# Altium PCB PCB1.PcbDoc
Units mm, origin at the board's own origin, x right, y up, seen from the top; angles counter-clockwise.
Board outline 64.06 x 116 mm, 2 copper layers (Top Layer, Bottom Layer); 43 components, 51 nets, 211 pads, 5 vias.
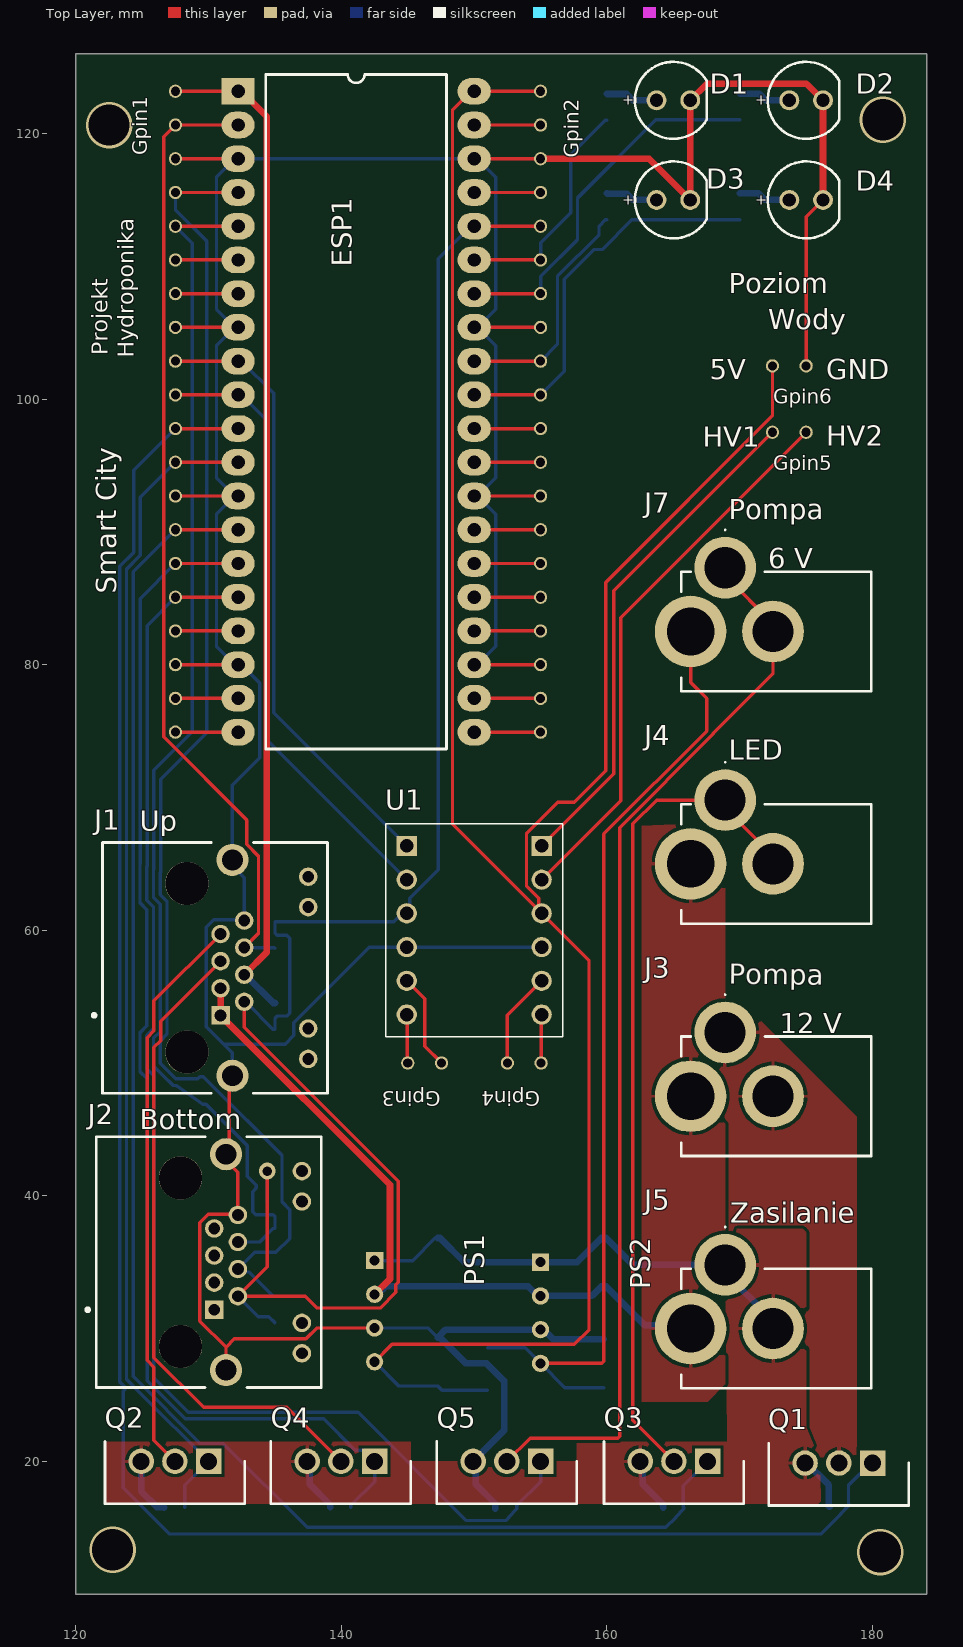
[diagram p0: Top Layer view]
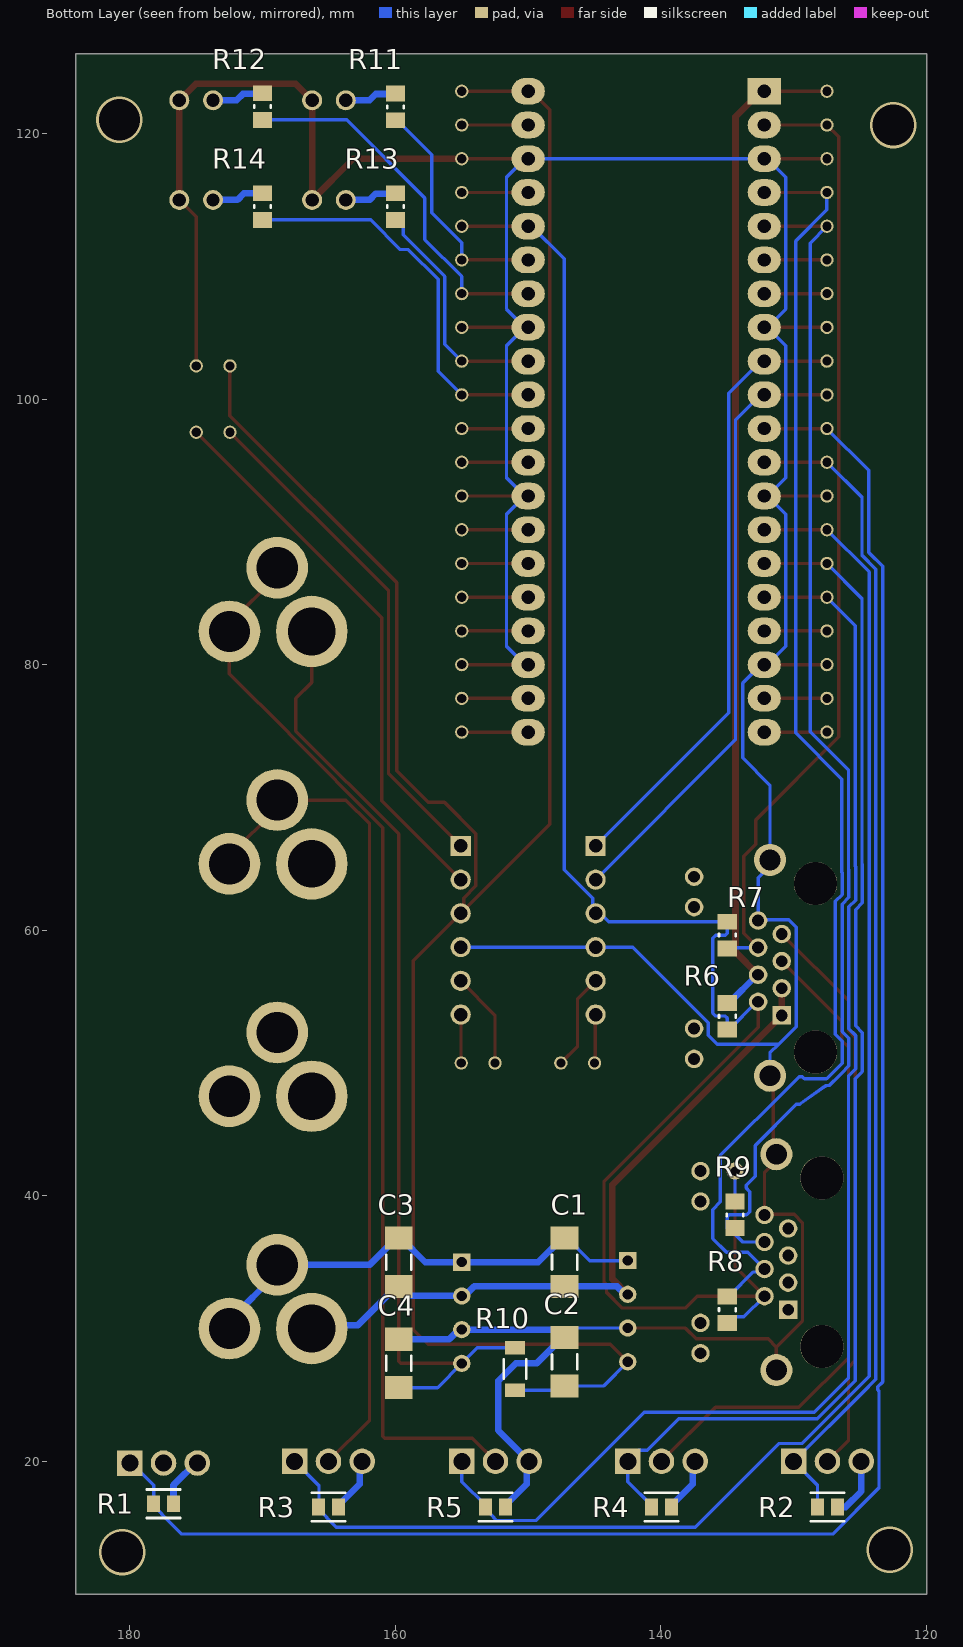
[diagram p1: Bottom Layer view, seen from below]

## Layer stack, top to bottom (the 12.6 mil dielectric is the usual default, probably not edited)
Top Solder: solder mask 0.0102, Solder Resist, Dk 3.5
Top Layer: signal copper 0.0356
Dielectric 1: dielectric 0.32, FR-4, Dk 4.8
Bottom Layer: signal copper 0.0356
Bottom Solder: solder mask 0.0102, Solder Resist, Dk 3.5

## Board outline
120,10 184.064,10 184.064,41.104 184.064,97.854 184.064,126 120,126

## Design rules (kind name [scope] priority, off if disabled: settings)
Clearance [All] p1: gap=0.254 ignorepadtopadclearanceinfootprint=FALSE
DiffPairsRouting [All] p1: maxlimit=0.254 minlimit=0.254 mostfreqgap=0.254 toplayer_minwidth=0.2 toplayer_maxwidth=0.381 toplayer_prefwidth=0.381 bottomlayer_minwidth=0.2 bottomlayer_maxwidth=0.381 bottomlayer_prefwidth=0.381 maxuncoupledlength=12.7
PolygonConnect [All] p1: connectstyle=Relief reliefconductorwidth=0.254 reliefentries=4 polygonreliefangle="90 Angle" airgapwidth=0.254
RoutingVias [All] p1: holewidth=0.711 width=1.27 viastyle="Through Hole" minholewidth=0.711 minwidth=1.27 maxholewidth=0.711 maxwidth=1.27
SolderMaskExpansion [All] p1: expansion=0.102 istentingtop=FALSE
SupplyNets "Schematic Supply Nets_3" [InNet('-vin_12')] p1: voltage=0.000
SupplyNets "Schematic Supply Nets_1" [InNet('- vout_5')] p2: voltage=0.000
SupplyNets "Schematic Supply Nets_8" [InNet('+vout_6')] p3: voltage=0.000
SupplyNets "Schematic Supply Nets_7" [InNet('+vin_12')] p4: voltage=0.000
SupplyNets "Schematic Supply Nets_6" [InNet('+vout_5')] p5: voltage=0.000
SupplyNets "Schematic Supply Nets" [InNet('3V3')] p6: voltage=0.000
Width [All] p1: maxlimit=6 minlimit=0.254 preferedwidth=0.254 minimp=50.000000 maximp=50.000000 favimp=50.000000 checkconnectedcopper=TRUE
29 further rules are at their usual default settings.

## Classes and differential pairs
component class "U_układ mocy": J3 J4 J7 Q1 Q2 Q3 Q4 Q5 R1 R2 R3 R4 R5
component class "U_12 na 5": C1 C2 C3 C4 J5 PS1 PS2 R10
component class Sheet1: D1 D2 D3 D4 ESP1 Gpin1 Gpin2 Gpin3 Gpin4 Gpin5 Gpin6 J1 J2 R6 R7 R8 R9 R11 R12 R13 R14 U1

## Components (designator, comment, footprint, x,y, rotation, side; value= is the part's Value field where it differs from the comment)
C1 "1000pF" CAPC4620X180X75LL50T35 147.25,35 r90 bottom
C2 "1000pF" CAPC4620X180X75LL50T35 147.25,27.5 r90 bottom
C3 "1000pF" CAPC4620X180X75LL50T35 159.75,35 r90 bottom
C4 "1000pF" CAPC4620X180X75LL50T35 159.75,27.38 r90 bottom
D1 "151053GS03000" WL-TMRW_D5.8H11.7 165,122.5 r0 top
D2 "151053GS03000" WL-TMRW_D5.8H11.7 175,122.5 r0 top
D3 "151053GS03000" WL-TMRW_D5.8H11.7 165,115 r0 top
D4 "151053GS03000" WL-TMRW_D5.8H11.7 175,115 r0 top
ESP1 "ESP32-S3-PICO" DIP40_ESP32 132.22,123.18 r0 top
Gpin1 "goldpin20" PCBComponent_1 127.5,100.32 r180 top
Gpin2 "goldpin20" PCBComponent_1 155,97.78 r0 top
Gpin3 "Goldpin 2" "Goldpin 2" 145,50 r270 top
Gpin4 "Goldpin 2" "Goldpin 2" 152.5,50 r270 top
Gpin5 "Goldpin 2" "Goldpin 2" 172.46,97.5 r270 top
Gpin6 "Goldpin 2" "Goldpin 2" 175,102.5 r90 top
J1 "2-406549-1" FP-2-406549-1-MFG 130.48,57.17 r270 top
J2 "2-406549-1" FP-2-406549-1-MFG 130,35 r270 top
J3 "PC-GK2.1" PCGK21 168.9,52.3 r180 top
J4 "PC-GK2.1" PCGK21 168.9,69.8 r180 top
J5 "PC-GK2.1" PCGK21 168.9,34.8 r180 top
J7 "PC-GK2.1" PCGK21 168.9,87.3 r180 top
PS1 "Isolated DC/DC Converters - Through Hole DC-DC CONVERTER, ISOLATED MODULE, SINGLE OUTPUT, 9.6V-14.4VDC INPUT, 5VDC OUTPUT, 1W   Source:  Datasheet" EC3T12S05P 142.5,35.12 r270 top
PS2 "Isolated DC/DC Converters - Through Hole DC-DC CONVERTER, ISOLATED MODULE, SINGLE OUTPUT, 9.6V-14.4VDC INPUT, 5VDC OUTPUT, 1W   Source:  Datasheet" EC3T12S05P 155,35 r270 top
Q1 "IRLZ44NPBF" TO254P469X1042X1967-3P 180,19.873 r180 top
Q2 "IRLZ44NPBF" TO254P469X1042X1967-3P 130,20 r180 top
Q3 "IRLZ44NPBF" TO254P469X1042X1967-3P 167.58,20 r180 top
Q4 "IRLZ44NPBF" TO254P469X1042X1967-3P 142.5,20 r180 top
Q5 "IRLZ44NPBF" TO254P469X1042X1967-3P 155,20 r180 top
R1 "ERA6AEB102V" FP-ERA6A-IPC_C 177.46,16.805 r180 bottom
R2 "ERA6AEB102V" FP-ERA6A-IPC_C 127.46,16.555 r180 bottom
R3 "ERA6AEB102V" FP-ERA6A-IPC_C 165.04,16.555 r180 bottom
R4 "ERA6AEB102V" FP-ERA6A-IPC_C 139.96,16.555 r180 bottom
R5 "ERA6AEB102V" FP-ERA6A-IPC_C 152.46,16.555 r180 bottom
R6 "RC0805FR-071KL" RESC2013X60X35ML10T20 135,53.52 r270 bottom
R7 "RC0805FR-071KL" RESC2013X60X35ML10T20 135,59.64 r90 bottom
R8 "RC0805FR-071KL" RESC2013X60X35ML10T20 135,31.42 r270 bottom
R9 "RC0805FR-071KL" RESC2013X60X35ML10T20 134.419,38.559 r90 bottom
R10 "AC1206JR-070RL" FP-AC1206-0_65-MFG 151,26.95 r90 bottom
R11 "RC0805FR-071KL" RESC2013X60X35ML10T20 160,122 r90 bottom
R12 "RC0805FR-071KL" RESC2013X60X35ML10T20 170,122.033 r90 bottom
R13 "RC0805FR-071KL" RESC2013X60X35ML10T20 160,114.5 r90 bottom
R14 "RC0805FR-071KL" RESC2013X60X35ML10T20 170,114.5 r90 bottom
U1 "BOB-12009" CONV_BOB-12009 150,60 r0 top

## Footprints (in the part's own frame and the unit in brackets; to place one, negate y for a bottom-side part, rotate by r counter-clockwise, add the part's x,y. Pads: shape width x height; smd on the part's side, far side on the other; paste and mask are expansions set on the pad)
CAPC4620X180X75LL50T35 [mm] "Chip Capacitor, 2-Leads, Body 5.1x2.2mm, IPC High Density"
  rect 1.75x2.1 smd: 1(-1.825,0) 2(1.825,0)
  silkscreen extent -0.55,-0.95 0.55,0.95, body extent -2.55,-1.1 2.55,1.1, height 1.8
CONV_BOB-12009 [mil]
  round 60 hole 40: GND_1(200,-50) GND_2(-200,-50) HV(200,50) HV2(200,150) HV3(200,-150) HV4(200,-250) LV(-200,50) LV2(-200,150) LV3(-200,-150) LV4(-200,-250)
  rect 60x60 / inner round 60 / far side rect 60x60 hole 40: HV1(200,250) LV1(-200,250)
  silkscreen extent -262,-316 262,316, body extent -262,-316 262,316, height 110
DIP40_ESP32 [mm]
  rect 2.5x2 hole 1: 1(0,0)
  oval 2.5x2 hole 1: 2(0,-2.54) 3(0,-5.08) 4(0,-7.62) 5(0,-10.16) 6(0,-12.7) 7(0,-15.24) 8(0,-17.78) 9(0,-20.32) 10(0,-22.86) 11(0,-25.4) 12(0,-27.94) 13(0,-30.48) 14(0,-33.02) 15(0,-35.56) 16(0,-38.1) 17(0,-40.64) 18(0,-43.18) 19(0,-45.72) 20(0,-48.26) 21(17.78,-48.26) 22(17.78,-45.72) 23(17.78,-43.18) 24(17.78,-40.64) 25(17.78,-38.1) 26(17.78,-35.56) 27(17.78,-33.02) 28(17.78,-30.48) 29(17.78,-27.94) 30(17.78,-25.4) 31(17.78,-22.86) 32(17.78,-20.32) 33(17.78,-17.78) 34(17.78,-15.24) 35(17.78,-12.7) 36(17.78,-10.16) 37(17.78,-7.62) 38(17.78,-5.08) 39(17.78,-2.54) 40(17.78,0)
  silkscreen extent 2.08,-49.53 15.7,1.27
EC3T12S05P [mm]
  rect 1.303x1.303 / inner round 1.204 / far side rect 1.303x1.303 hole 0.76: 1(0,0)
  round 1.303 hole 0.76: 2(2.54,0) 3(5.08,0) 4(7.62,0)
FP-2-406549-1-MFG [mm]
  rect 1.39x1.39 hole 0.89 paste-2539.97 mask+0: 1(3.58,0.42)
  round 1.39 hole 0.89 paste-2539.97 mask+0: 2(2.56,2.2) 3(1.54,0.42) 4(0.52,2.2) 5(-0.5,0.42) 6(-1.52,2.2) 7(-2.54,0.42) 8(-3.56,2.2) 9(-6.86,7.02) 10(-4.57,7.02) 11(4.57,7.02) 12(6.86,7.02)
  round 2.42 hole 1.57 paste-2539.97 mask+0: 13(-8.13,1.31) 14(8.13,1.31)
  round 3.25 hole 3.25 unplated paste-2539.97 mask+0: ""(-6.35,-2.12) ""(6.35,-2.12)
  silkscreen extent -9.44,-9.23 9.44,8.47, body extent -9.53,-8.57 9.53,8.57, height 0.25
FP-AC1206-0_65-MFG [mm]
  rect 1x1.5 smd paste+0 mask+0: 1(-1.6,0) 2(1.6,0)
  silkscreen extent -0.72,-0.85 0.72,0.85, body extent -1.55,-0.8 1.55,0.8, height 0.65
FP-ERA6A-IPC_C [mm]
  rect 1.005x1.262 smd paste+0 mask+0: 1(-0.751,0) 2(0.751,0)
  silkscreen extent -1.25,-1.07 1.25,1.07, body extent -1,-0.63 1,0.63, height 0.6
"Goldpin 2" [mm]
  round 1 / inner round 2.42 / far side round 1 hole 0.69 paste-2539.97 mask+0: 1(0,0) 2(0,2.54)
  body extent -1.27,-1.27 1.27,3.81, height 6.8
PCBComponent_1 [mm]
  round 1 / inner round 2.42 / far side round 1 hole 0.69 paste-2539.97 mask+0: 1(0,25.4) 2(0,22.86) 3(0,20.32) 4(0,17.78) 5(0,15.24) 6(0,12.7) 7(0,10.16) 8(0,7.62) 9(0,5.08) 10(0,2.54) 11(0,0) 12(0,-2.54) 13(0,-5.08) 14(0,-7.62) 15(0,-10.16) 16(0,-12.7) 17(0,-15.24) 18(0,-17.78) 19(0,-20.32) 20(0,-22.86)
  body extent -1.27,-24.13 1.27,26.67, height 6.8
PCGK21 [mm]
  round 4.65 hole 3.1: 2(0,0) 3(-3.6,4.8)
  round 5.385 hole 3.59: 4(2.6,4.8)
  silkscreen extent -11,-2.9 3.3,9.3, body extent -10.92,-0.09 3.38,9.33, height 12.54
RESC2013X60X35ML10T20 [mm] "Chip Resistor, 2-Leads, Body 2.1x1.35mm, IPC Low Density"
  rect 1.2x1.45 smd: 1(-1,0) 2(1,0)
  silkscreen extent -0.1,-0.63 0.1,0.63, body extent -1.05,-0.68 1.05,0.67, height 0.6
TO254P469X1042X1967-3P [mm]
  rect 1.92x1.92 hole 1.28: 1(0,0)
  round 1.92 hole 1.28: 2(2.54,0) 3(5.08,0)
  silkscreen extent -2.73,-1.5 7.81,3.19, body extent -2.67,-1.5 7.75,3.19, height 18.84
WL-TMRW_D5.8H11.7 [mm] "THT Mono-color Round LED, 2-leads"
  round 1.5 hole 1: 1(1.27,0) 2(-1.27,0)
  silkscreen extent -2.9,-2.9 2.5,2.9, body extent -2.9,-2.9 2.5,2.9, height 11.7

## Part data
C1 C2 C3 C4: library part CMP-2000-05503-1, "Chip Capacitor, 1000 pF, +/- 10%, 2000 V, -55 to 125 degC, 1808 (4520 Metric), RoHS, Tape and Reel", Capacitance=1nF, Case Size/Dimension=1808, Dielectric=X7R, Manufacturer=AVX, Package Description="2-Pin Surface Mount Device, Body 4.6 x 2 mm", Rated Voltage=2000V, Tolerance (%)=±10%
D1 D2 D3 D4: library part CMP-1489-00005-2, Case/Package=Radial, Color=Green, Forward Current=100mA, Forward Voltage=3.4V, Max Operating Temperature=85°C, Max Reverse Voltage (DC)=5V, Min Operating Temperature=-40°C, Test Current=20mA
J1 J2: library part CMP-2000-05541-2, "CONN MOD JACK 8P8C R/A SHIELDED", Color=Yellow, Current Rating=1.5A, Flammability Rating="UL94 V-0", Housing Color=Black, Max Operating Temperature=85°C, Max Voltage Rating (AC)=150V, Min Operating Temperature=-40°C, Package Quantity=63
J3 J4 J5 J7: "Connector", Manufacturer_Name=Ninigi
PS1 PS2: library part EC3T-12S05P, Manufacturer_Name="Adam Tech", Package=EC3T12S05P
Q1 Q2 Q3 Q4 Q5: "MOSFET (N-Channel)", Manufacturer_Name=Infineon, Mouser Part Number=942-IRLZ44NPBF
R1 R2 R3 R4 R5: library part CMP-2001-00581-2, "RES 1K OHM 0.1% 1/8W 0805", Case Code (Imperial)=0805, Case Code (Metric)=2012, Max Operating Temperature=155°C, Max Power Dissipation=125mW, Min Operating Temperature=-55°C, Package Quantity=5000, Resistance=1kR, Resistance Tolerance=0.1%, Resistor Type="Thin Film", Temperature Coefficient=25ppm/°C, Voltage Rating=100V
R6 R7 R8 R9 R11 R12 R13 R14: library part CMP-2100-03671-1, "Chip Resistor, 1 KOhm, +/- 1%, 125 mW, -55 to 155 degC, 0805 (2012 Metric), RoHS, Tape and Reel", Case Code (Imperial)=0805, Case Code (Metric)=2012, Manufacturer=Yageo, Max Operating Temperature=155degC, Max Power Dissipation=125mW, Min Operating Temperature=-55degC, Package Description="2-Pin Surface Mounted Device, Body 2 x 1.25 mm", Package Quantity=1, Resistance=1KOhm, Temperature Coefficient=100ppm/degreesC, Tolerance=1%, Voltage Rating=150V
R10: library part CMP-2003-04900-2, "RES SMD 0 OHM JUMPER 1/4W 1206", Case Code (Imperial)=1206, Case Code (Metric)=3216, Max Operating Temperature=155°C, Max Power Dissipation=250mW, Min Operating Temperature=-55°C, Package Quantity=5000, Resistance=0R, Resistor Type="Thick Film", Temperature Coefficient=200ppm/°C, Tolerance=5%, Voltage Rating=200V
U1: "BSS138 - Logic-Level Translator Interface Evaluation Board", Package=None

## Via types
v1: diameter 3.5, hole 3.1, Top Layer to Bottom Layer, 4 vias
v2: diameter 1.27, hole 0.72, Top Layer to Bottom Layer, 1 vias

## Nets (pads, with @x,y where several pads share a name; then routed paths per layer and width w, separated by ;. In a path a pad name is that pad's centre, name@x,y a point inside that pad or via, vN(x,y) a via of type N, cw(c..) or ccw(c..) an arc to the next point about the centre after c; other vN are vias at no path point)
3V3: ESP1.36 Gpin2.5 J1.2 J2.2 R6.2 R7.2 R8.2 R9.2 U1.LV | length 138.1
  Top Layer w0.254: J1.2 132.68,52.702 144.287,41.096 144.287,33.474 144.102,33.289 144.102,32.722 142.928,31.547 138.164,31.547 137.271,32.44 J2.2 134.419,34.659 v2(134.419,41.86) ; ESP1.36 Gpin2.5
  Bottom Layer w0.254: J2.2 133.747,30.893 134.527,30.893 R8.2 ; J1.2 132.785,54.61 134.875,52.52 R6.2 135,53.39 135.149,53.539 135.883,53.539 136.106,53.762 136.106,59.398 135.883,59.621 135.149,59.621 135,59.77 R7.2 143.946,60.64 144.576,61.27 U1.LV 145.139,61.489 145.139,62.413 147.289,64.563 147.289,110.559 149.75,113.02 ESP1.36 ; R9.2 v2(134.419,41.86)
+vin_12: C1.1 C3.1 J1.1 J1.3 J3.4 J4.4 J5.4 PS1.2 PS2.2 | length 54.8
  Top Layer w0.5: J1.1@130.9,53.547 J1.3 ; J1.1 143.656,40.834 143.656,33.736 PS1.2
  Bottom Layer w0.5: PS1.2 142.717,32.58 143.312,33.175 C1.1 154.068,33.175 154.783,32.46 PS2.2 158.86,32.46 159.575,33.175 C3.1 159.925,33.175 162.858,30.243 166.057,30.243 J5.4
+vout_5: C2.1 ESP1.40 Gpin2.1 Gpin6.2 PS1.4 R10.1 U1.HV | length 180
  Top Layer w0.254: PS1.4 143.81,28.81 157.54,28.81 158.65,29.92 158.65,57.7 U1.HV ; Gpin2.1 ESP1.40 149.75,123.18 148.369,121.799 148.369,67.981 U1.HV ; Gpin6.2 172.46,98.746 159.901,86.187 159.901,71.997 157.538,69.634 156.301,69.634 153.937,67.27 153.937,63.337 154.861,62.413 154.861,61.489 U1.HV
  Bottom Layer w0.254: PS1.4 144.325,25.675 C2.1 147.575,25.35 R10.1
+vout_6: C4.1 J7.4 PS2.4 R10.2 | length 73.5
  Top Layer w0.254: PS2.4 159.601,27.38 159.75,27.529 159.75,67.25 167.5,75 167.5,77.456 166.3,78.656 J7.4
  Bottom Layer w0.254: R10.2 153.83,28.55 PS2.4 156.825,25.555 C4.1
"- duży wiatrak": J1.5 Q4.2 | length 49.3
  Top Layer w0.254: J1.5 126.382,53.152 126.382,51.679 125.874,51.171 125.874,27.819 129.624,24.069 135.891,24.069 Q4.2
"- mały wiatrak": J1.7 Q2.2 | length 42.9
  Top Layer w0.254: Q2.2 125.874,21.586 125.874,27.101 125.366,27.609 125.366,51.909 125.874,52.417 125.874,54.684 J1.7
"- vout_5": C2.2 C4.2 D1.1 D2.1 D3.1 D4.1 ESP1.3 ESP1.8 ESP1.13 ESP1.18 ESP1.23 ESP1.28 ESP1.33 ESP1.38 Gpin1.3 Gpin1.8 Gpin1.13 Gpin1.18 Gpin2.3 Gpin2.8 Gpin2.13 Gpin2.18 Gpin6.1 J1.8 J1.13 J1.14 J2.8 J2.13 J2.14 PS1.3 PS2.3 Q5.3 R5.2 U1.GND_1 U1.GND_2 | length 331
  Top Layer w0.254: Gpin1.3 ESP1.18 ; Gpin1.8 ESP1.13 ; Gpin1.13 ESP1.8 ; Gpin1.18 ESP1.3 ; J2.14 131.31,28.601 ; J1.14 131.55,48.8 131.55,43.37 J2.13 131.31,42.66 132.2,41.77 J2.8 132.144,38.616 129.974,38.616 129.344,37.986 129.344,30.567 131.31,28.601 ; PS1.3@142.56,29.98 PS1.3 138.152,30.04 137.332,29.22 131.929,29.22 131.31,28.601 ; ESP1.23 Gpin2.18 ; ESP1.28 Gpin2.13 ; ESP1.33 Gpin2.8 ; ESP1.38 Gpin2.3 ; Gpin6.1 175,113.73 D4.1
  Top Layer w0.5: Gpin2.3 163.17,118.1 D3.1 D1.1 167.524,123.754 175.016,123.754 D2.1 D4.1
  Bottom Layer w0.254: J1.14 131.79,50.771 131.141,51.42 ; ESP1.13 ESP1.13@131.97,92.7 ; ESP1.8 ESP1.8@131.97,105.4 ; PS1.3 146.535,30.04 C2.2 ; ESP1.23 150.25,80 151.631,81.381 151.631,91.319 ESP1.28@150.25,92.7 ; ESP1.28 ESP1.28@150.25,92.7 ; ESP1.33 ESP1.33@150.25,105.4 ; U1.GND_1 U1.GND_2 142.108,58.73 136.424,53.046 136.424,52.08 135.764,51.42 131.141,51.42 ; 131.141,51.42 129.824,52.737 129.824,60.236 130.374,60.786 132.624,60.786 J1.8 132.68,63.94 131.79,64.83 J1.13 131.79,70.929 133.851,72.99 133.851,78.619 132.47,80 ESP1.18 131.97,80 130.589,81.381 130.589,91.319 ESP1.13@131.97,92.7 ; ESP1.13@131.97,92.7 130.589,94.081 130.589,104.019 ESP1.8@131.97,105.4 ; ESP1.8@131.97,105.4 130.589,106.781 130.589,116.719 131.97,118.1 ESP1.3 ESP1.38 150.25,118.1 151.631,116.719 151.631,106.781 ESP1.33@150.25,105.4 ; ESP1.28@150.25,92.7 151.631,94.081 151.631,104.019 ESP1.33@150.25,105.4
  Bottom Layer w0.5: R5.2@151.59,16.449 151.59,16.803 150.103,18.29 150.103,19.817 Q5.3 152.254,22.334 152.254,26.059 150.933,27.379 149.371,27.379 147.425,29.325 C2.2 147.845,29.92 PS2.3 155.217,29.92 155.932,29.205 C4.2
-vin_12: C1.2 C3.2 J5.2 J5.3 PS1.1 PS2.1 Q1.3 Q2.3 Q3.3 Q4.3 R1.2 R2.2 R3.2 R4.2 | length 52.6
  Bottom Layer w0.254: PS1.1 145.37,35.12 147.075,36.825 C1.2
  Bottom Layer w0.5: Q2.3 124.92,17.742 126.107,16.555 126.606,16.555 R2.2@126.641,16.521 ; Q4.3 137.603,19.817 137.603,18.29 139.158,16.735 R4.2@139.158,16.535 ; C1.2 147.425,36.825 149.25,35 PS2.1 157.75,35 159.575,36.825 C3.2 ; C3.2@159.925,36.825 161.95,34.8 J5.2 168.9,34.2 172.5,30.6 J5.3 ; Q3.3 162.683,19.817 162.683,18.29 164.231,16.742 R3.2@164.231,16.528 ; Q1.3@174.92,20 176.709,18.211 176.709,16.642 R1.2@176.761,16.59
LED1: ESP1.35 Gpin2.6 R11.1 | length 17.7
  Top Layer w0.254: ESP1.35 Gpin2.6
  Bottom Layer w0.254: Gpin2.6 155,111.774 157.272,114.046 157.272,118.397 159.875,121 R11.1
LED2: ESP1.34 Gpin2.7 R12.1 | length 28
  Top Layer w0.254: ESP1.34 Gpin2.7
  Bottom Layer w0.254: Gpin2.7 155,109.234 157.78,112.014 157.78,115.144 163.669,121.033 R12.1
LED3: ESP1.32 Gpin2.9 R13.1 | length 17.8
  Top Layer w0.254: ESP1.32 Gpin2.9
  Bottom Layer w0.254: Gpin2.9 156.27,104.13 156.27,109.234 159.402,112.366 159.402,113.027 159.875,113.5 R13.1
LED4: ESP1.31 Gpin2.10 R14.1 | length 29.5
  Top Layer w0.254: ESP1.31 Gpin2.10
  Bottom Layer w0.254: Gpin2.10 156.778,102.098 156.778,109.024 159.016,111.262 159.626,111.262 161.864,113.5 R14.1
LV1: ESP1.9 Gpin1.12 U1.LV1 | length 46.6
  Top Layer w0.254: Gpin1.12 ESP1.9
  Bottom Layer w0.254: ESP1.9 132.47,102.86 134.895,100.435 134.895,76.375 U1.LV1
LV2: ESP1.10 Gpin1.11 U1.LV2 | length 46.6
  Top Layer w0.254: Gpin1.11 ESP1.10
  Bottom Layer w0.254: ESP1.10 132.47,100.32 134.387,98.403 134.387,74.343 U1.LV2
NetD1_2: D1.2 R11.2 | length 3.9
  Bottom Layer w0.5: R11.2 160.028,122.972 161.475,122.972 161.947,122.5 D1.2
NetD2_2: D2.2 R12.2 | length 4
  Bottom Layer w0.5: R12.2 170.045,122.988 171.475,122.988 171.963,122.5 D2.2
NetD3_2: D3.2 R13.2 | length 3.9
  Bottom Layer w0.5: R13.2 160.028,115.472 161.475,115.472 161.947,115 D3.2
NetD4_2: D4.2 R14.2 | length 3.9
  Bottom Layer w0.5: R14.2 171.4,115.5 171.9,115 D4.2
NetESP1_6: ESP1.6 Gpin1.15 | length 4.7
  Top Layer w0.254: Gpin1.15 ESP1.6
NetESP1_7: ESP1.7 Gpin1.14 | length 4.7
  Top Layer w0.254: Gpin1.14 ESP1.7
NetESP1_17: ESP1.17 Gpin1.4 | length 4.7
  Top Layer w0.254: Gpin1.4 ESP1.17
NetESP1_19: ESP1.19 Gpin1.2 | length 4.7
  Top Layer w0.254: Gpin1.2 ESP1.19
NetESP1_20: ESP1.20 Gpin1.1 | length 4.7
  Top Layer w0.254: Gpin1.1 ESP1.20
NetESP1_21: ESP1.21 Gpin2.20 | length 5
  Top Layer w0.254: ESP1.21 Gpin2.20
NetESP1_22: ESP1.22 Gpin2.19 | length 5
  Top Layer w0.254: ESP1.22 Gpin2.19
NetESP1_24: ESP1.24 Gpin2.17 | length 5
  Top Layer w0.254: ESP1.24 Gpin2.17
NetESP1_25: ESP1.25 Gpin2.16 | length 5
  Top Layer w0.254: ESP1.25 Gpin2.16
NetESP1_26: ESP1.26 Gpin2.15 | length 5
  Top Layer w0.254: ESP1.26 Gpin2.15
NetESP1_27: ESP1.27 Gpin2.14 | length 5
  Top Layer w0.254: ESP1.27 Gpin2.14
NetESP1_29: ESP1.29 Gpin2.12 | length 5
  Top Layer w0.254: ESP1.29 Gpin2.12
NetESP1_30: ESP1.30 Gpin2.11 | length 5
  Top Layer w0.254: ESP1.30 Gpin2.11
NetESP1_37: ESP1.37 Gpin2.4 | length 5
  Top Layer w0.254: ESP1.37 Gpin2.4
NetESP1_39: ESP1.39 Gpin2.2 | length 5
  Top Layer w0.254: ESP1.39 Gpin2.2
NetGpin3_1: Gpin3.1 U1.LV4 | length 3.7
  Top Layer w0.254: U1.LV4 144.96,53.61 144.96,50.04 Gpin3.1
NetGpin3_2: Gpin3.2 U1.LV3 | length 7.3
  Top Layer w0.254: U1.LV3 146.28,54.83 146.28,51.26 Gpin3.2
NetGpin4_1: Gpin4.1 U1.HV3 | length 7.3
  Top Layer w0.254: Gpin4.1 152.5,53.61 U1.HV3
NetGpin4_2: Gpin4.2 U1.HV4 | length 3.7
  Top Layer w0.254: Gpin4.2 155.06,50.02 155.06,53.63 U1.HV4
NetGpin5_1: Gpin5.1 U1.HV1 | length 38.3
  Top Layer w0.254: U1.HV1 160.517,71.787 160.517,85.557 Gpin5.1
NetGpin5_2: Gpin5.2 U1.HV2 | length 41.9
  Top Layer w0.254: U1.HV2 161.025,69.755 161.025,83.525 Gpin5.2
SCL_dół: ESP1.5 Gpin1.16 J2.6 R9.1 | length 90.8
  Top Layer w0.254: Gpin1.16 ESP1.5
  Bottom Layer w0.254: Gpin1.16 128.77,111.75 128.77,74.944 125.874,72.048 125.874,64.589 125.846,64.561 125.846,62.479 126.354,61.971 126.354,52.369 125.846,51.861 125.846,49.779 126.382,49.243 126.582,49.042 127.319,48.306 127.479,48.306 cw(c127.479,48.052) 127.625,48.26 ; 127.626,48.259 129.559,46.889 129.801,46.889 132.901,43.789 132.901,41.479 133.583,40.797 133.583,40.587 133.313,40.317 133.313,38.801 133.555,38.559 134.851,38.559 135,38.41 135,37.54 134.875,37.54 133.855,36.52 J2.6
SCL_góra: ESP1.2 Gpin1.19 J1.6 R7.1 | length 72.8
  Top Layer w0.254: ESP1.2 Gpin1.19 126.619,119.759 126.619,74.555 132.873,68.301 132.873,66.467 133.756,65.584 133.756,59.766 J1.6
  Bottom Layer w0.254: J1.6 134.95,58.69 R7.1
SDA_dół: ESP1.4 Gpin1.17 J2.4 R8.1 | length 100.3
  Top Layer w0.254: Gpin1.17 ESP1.4
  Bottom Layer w0.254: Gpin1.17 127.5,114.266 129.86,111.906 129.86,74.86 126.382,71.382 126.382,64.379 126.354,64.351 126.354,62.689 126.862,62.181 126.862,52.159 126.354,51.651 126.354,49.989 127.529,48.814 129.191,48.814 129.346,48.969 129.595,48.969 130.199,48.364 135.525,43.038 135.525,39.543 136.106,38.962 136.106,36.782 135.064,35.74 133.46,35.74 J2.4 132.417,34.263 133.032,34.263 134.875,32.42 R8.1
SDA_góra: ESP1.1 Gpin1.20 J1.4 R6.1 | length 76.2
  Top Layer w0.254: Gpin1.20 ESP1.1
  Top Layer w0.5: ESP1.1 132.47,123.18 134.387,121.263 134.387,58.357 J1.4
  Bottom Layer w0.5: J1.4 132.745,56.65 134.875,54.52 R6.1
"Ster. LED": ESP1.14 Gpin1.7 Q3.1 R3.1 | length 120.9
  Top Layer w0.254: Gpin1.7 ESP1.14
  Bottom Layer w0.254: Gpin1.7 124.322,86.982 124.322,26.399 129.38,21.341 131.118,21.341 137.424,15.035 164.441,15.035 165.173,15.766 165.173,15.808 165.791,16.426 R3.1 ; R3.1@165.752,16.559 165.752,18.172 Q3.1
"Ster. Pompa": ESP1.11 Gpin1.10 Q1.1 R1.1 | length 147.5
  Top Layer w0.254: Gpin1.10 ESP1.11
  Bottom Layer w0.254: Gpin1.10 124.35,94.63 124.35,88.447 123.306,87.403 123.306,25.978 123.678,25.606 123.678,25.395 123.579,25.296 123.579,18.013 127.065,14.527 176.103,14.527 177.593,16.016 177.593,16.058 178.211,16.676 R1.1 ; R1.1@178.188,16.805 178.188,18.188 Q1.1@180,20
"Ster. Wiatrak duży": ESP1.15 Gpin1.6 Q4.1 R4.1 | length 91.9
  Top Layer w0.254: Gpin1.6 ESP1.15
  Bottom Layer w0.254: Gpin1.6 124.858,84.978 124.858,65.01 124.83,64.982 124.83,62.058 125.338,61.55 125.338,52.79 124.83,52.282 124.83,49.358 125.366,48.822 125.366,26.89 125.366,26.073 128.24,23.199 138.657,23.199 141.023,20.833 141.667,20.833 Q4.1 142.5,18.473 140.711,16.684 R4.1
"Ster. Wiatrak mały": ESP1.12 Gpin1.9 Q2.1 R2.1 | length 88.2
  Top Layer w0.254: Gpin1.9 ESP1.12
  Bottom Layer w0.254: Gpin1.9 124.858,92.598 124.858,88.236 123.814,87.192 123.814,26.188 124.858,25.144 124.858,25.142 Q2.1 128.211,18.211 R2.1
sterowanie_pompa2: ESP1.16 Gpin1.5 Q5.1 R5.1 | length 101.5
  Top Layer w0.254: Gpin1.5 ESP1.16
  Bottom Layer w0.254: Gpin1.5 125.366,82.946 125.366,64.8 125.338,64.772 125.338,62.268 125.846,61.76 125.846,52.58 125.338,52.072 125.338,49.568 125.874,49.032 125.874,26.283 128.45,23.707 141.252,23.707 149.416,15.543 152.369,15.543 152.593,15.766 152.593,15.808 153.211,16.426 R5.1 153.211,16.684 155,18.473 Q5.1
wyj_LED: J4.2 J4.3 Q3.2 | length 63.3
  Top Layer w0.254: Q3.2 161.947,23.093 161.947,68.011 163.737,69.8 J4.2 168.9,69.2 172.5,65.6 J4.3
wyj_pompa: J3.2 J3.3 Q1.2
wyj_pompa2: J7.2 J7.3 Q5.2 | length 81
  Top Layer w0.254: Q5.2 154.205,21.745 160.801,21.745 160.95,21.894 160.95,67.732 168.008,74.79 168.008,74.833 172.5,79.325 J7.3 172.5,83.1 168.9,86.7 J7.2
pads on no net: J1. J1.9 J1.10 J1.11 J1.12 J2. J2.1 J2.3 J2.5 J2.7 J2.9 J2.10 J2.11 J2.12
copper on no net:
  other v1: 180.576,13.172 122.769,13.349 122.5,120.64 180.782,121.039

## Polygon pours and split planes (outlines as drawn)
no net on Layer0 "Default Coverlay 1 Top" (split plane): 120,22 182,22 182,126 120,126
no net on Layer0 "Default Coverlay 1 Bottom" (split plane): 120,22 182,22 182,126 120,126
-vin_12 on Top Layer "-VIN_12_L01_P006" (solid, pour order 6): 122.19,21.495 145.23,21.495 145.23,20 159.77,20 159.77,16.805 122.19,16.805
wyj_pompa on Top Layer "WYJ_POMPA_L01_P005" (solid, remove dead copper, pour order 5): 167.908,54.694 169.13,36.184 175.811,20 178.813,20 178.813,45.937 169.847,54.903
+vin_12 on Top Layer "+VIN_12_L01_P001" (solid, remove dead copper, pour order 1): 162.607,67.857 162.607,24.5 167.58,24.5 168.9,25.82 168.9,68.157
-vin_12 on Top Layer "-VIN_12_L01_P004" (solid, pour order 4): 168.9,37.391 169.009,37.5 175.829,37.5 176.104,16.805 157.73,16.805 157.73,21.495 169.04,21.495

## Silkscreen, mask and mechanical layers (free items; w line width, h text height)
Top Overlay:
  text "Poziom" at 169.154,107.954 h1.52
  text "Wody" at 172.154,105.262 h1.52
  text "Projekt" at 122.41,103.287 h1.2 r90
  text "Hydroponika" at 124.346,103.114 h1.2 r90
  text "5V" at 167.754,101.484 h1.52
  text "GND" at 176.524,101.484 h1.52
  text "HV2" at 176.524,96.484 h1.52
  text "HV1" at 167.206,96.404 h1.52
  text "Pompa" at 169.154,90.962 h1.52
  text "6 V" at 172.154,87.254 h1.52
  text "Smart City" at 123.06,85.334 h1.5 r90
  text "LED" at 169.154,72.854 h1.52
  text "Up" at 124.83,67.5 h1.52
  text "Pompa" at 169.163,55.959 h1.52 r359.29
  text "12 V" at 173.004,52.254 h1.52
  text "Bottom" at 124.83,45 h1.52
  text "Zasilanie" at 169.284,37.954 h1.52
Mechanical 1:
  lines w1.2: 184.064,9.979 184.064,41.104 184.064,97.854 184.064,126 120,126 120,10 184.064,10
